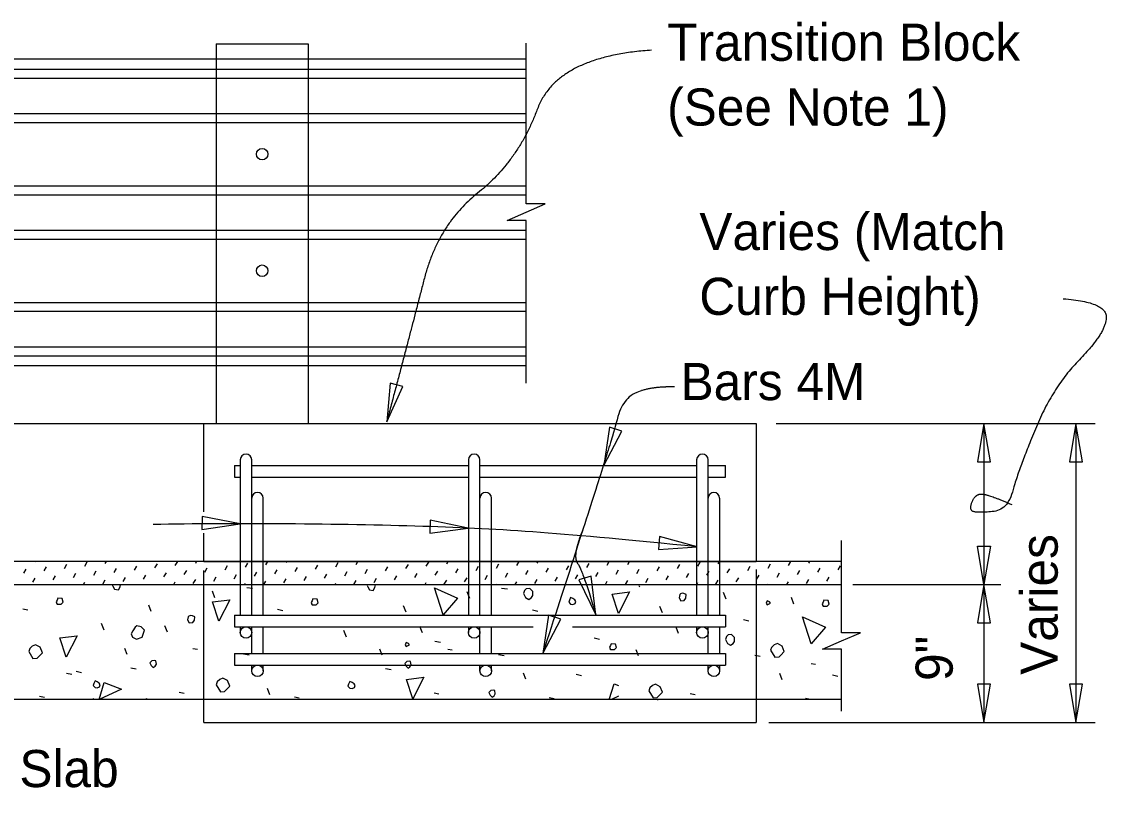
# Model space of a CAD drawing. Extents: x 21526.6 to 21595.9, y 56117 to 56157.3.
# Drawn here: x 21561.42 to 21567.31, y 56133.17 to 56137.39 of the extents above; entities that cross this region are included whole.
import ezdxf

# ---------------------------------------------------------------- set-up
doc = ezdxf.new("R2010")
doc.units = 0
for name, color, linetype in [('AdhocPoint_dp', 7, 'Continuous'), ('Border', 7, 'Continuous'), ('Patterning', 7, 'Continuous'), ('PlotBorder_dp', 7, 'Continuous'), ('SheetBorder_dp', 7, 'Continuous'), ('SheetLines_dp', 7, 'Continuous'), ('SubStrConc', 7, 'Continuous'), ('SubStrConc_h', 7, 'Continuous')]:
    doc.layers.add(name, color=color, linetype=linetype)

msp = doc.modelspace()

# ---------------------------------------------------------------- linework, layer by layer
at = {"layer": 'AdhocPoint_dp'}
for p, q in [((21554.3018, 56135.21), (21562.4118, 56135.21)), ((21565.8764, 56134.4601), (21554.3018, 56134.4601)), ((21554.3018, 56134.3351), (21565.8764, 56134.3351)), ((21565.8764, 56133.71), (21559.5217, 56133.71))]:
    msp.add_line(p, q, dxfattribs=at)
at = {"layer": 'Patterning'}
for p, q in [((21562.4788, 56137.2725), (21562.4788, 56135.21)), ((21562.4788, 56137.2725), (21562.9788, 56137.2725)), ((21562.9788, 56137.2725), (21562.9788, 56135.21)), ((21552.8484, 56137.1336), (21564.1633, 56137.1336)), ((21552.8484, 56137.0853), (21564.1633, 56137.0853)), ((21552.8484, 56136.8925), (21564.1633, 56136.8925)), ((21552.8484, 56136.8443), (21564.1633, 56136.8443)), ((21552.8484, 56136.5003), (21564.1633, 56136.5003)), ((21552.8484, 56136.4521), (21564.1633, 56136.4521)), ((21552.8484, 56136.2593), (21564.1633, 56136.2593)), ((21552.8484, 56136.2112), (21564.1633, 56136.2112)), ((21552.8484, 56135.8672), (21564.1633, 56135.8672)), ((21552.8484, 56135.819), (21564.1633, 56135.819)), ((21552.8484, 56135.6262), (21564.1633, 56135.6262)), ((21552.8484, 56135.5779), (21564.1633, 56135.5779)), ((21561.4336, 56134.3964), (21561.4465, 56134.4187)), ((21561.4954, 56134.4582), (21561.4965, 56134.4601)), ((21561.5442, 56134.4093), (21561.5572, 56134.4317)), ((21561.6548, 56134.4223), (21561.6678, 56134.4447)), ((21561.7655, 56134.4352), (21561.7784, 56134.4576)), ((21561.8761, 56134.4482), (21561.883, 56134.4601)), ((21561.9249, 56134.3994), (21561.9379, 56134.4218)), ((21562.0356, 56134.4123), (21562.0485, 56134.4347)), ((21562.1462, 56134.4253), (21562.1592, 56134.4477)), ((21562.2568, 56134.4383), (21562.2695, 56134.4601)), ((21562.3675, 56134.4512), (21562.3726, 56134.4601)), ((21562.4163, 56134.4024), (21562.4293, 56134.4248)), ((21562.5269, 56134.4154), (21562.5399, 56134.4377)), ((21562.6376, 56134.4283), (21562.6505, 56134.4507)), ((21562.7482, 56134.4413), (21562.7591, 56134.4601)), ((21562.8588, 56134.4542), (21562.8622, 56134.4601)), ((21562.9077, 56134.4054), (21562.9206, 56134.4278)), ((21563.0183, 56134.4184), (21563.0312, 56134.4408)), ((21563.1289, 56134.4313), (21563.1419, 56134.4537)), ((21563.2396, 56134.4443), (21563.2487, 56134.4601)), ((21563.2884, 56134.3955), (21563.3013, 56134.4179)), ((21563.3502, 56134.4573), (21563.3518, 56134.4601)), ((21563.399, 56134.4084), (21563.412, 56134.4308)), ((21563.5097, 56134.4214), (21563.5226, 56134.4438)), ((21563.6203, 56134.4344), (21563.6332, 56134.4568)), ((21563.7309, 56134.4473), (21563.7383, 56134.4601)), ((21563.7798, 56134.3985), (21563.7927, 56134.4209)), ((21563.8904, 56134.4115), (21563.9033, 56134.4338)), ((21564.001, 56134.4244), (21564.014, 56134.4468)), ((21564.1116, 56134.4374), (21564.1246, 56134.4598)), ((21564.2223, 56134.4503), (21564.2279, 56134.4601)), ((21564.2711, 56134.4015), (21564.2841, 56134.4239)), ((21564.3817, 56134.4145), (21564.3947, 56134.4369)), ((21564.4924, 56134.4274), (21564.5053, 56134.4498)), ((21564.603, 56134.4404), (21564.6144, 56134.4601)), ((21564.7151, 56134.4443), (21564.7243, 56134.4601)), ((21564.764, 56134.3955), (21564.7769, 56134.4179)), ((21564.8258, 56134.4573), (21564.8274, 56134.4601)), ((21564.8746, 56134.4084), (21564.8876, 56134.4308)), ((21564.9852, 56134.4214), (21564.9982, 56134.4438)), ((21565.0959, 56134.4344), (21565.1088, 56134.4568)), ((21565.2065, 56134.4473), (21565.2139, 56134.4601)), ((21565.2553, 56134.3985), (21565.2683, 56134.4209)), ((21565.366, 56134.4115), (21565.3789, 56134.4338)), ((21565.4766, 56134.4244), (21565.4896, 56134.4468)), ((21565.5872, 56134.4374), (21565.6002, 56134.4598)), ((21565.6979, 56134.4503), (21565.7035, 56134.4601)), ((21565.7467, 56134.4015), (21565.7597, 56134.4239)), ((21565.8573, 56134.4145), (21565.8703, 56134.4369)), ((21561.4824, 56134.3475), (21561.4954, 56134.3699)), ((21561.593, 56134.3605), (21561.606, 56134.3829)), ((21561.7037, 56134.3734), (21561.7166, 56134.3958)), ((21561.8143, 56134.3864), (21561.8273, 56134.4088)), ((21561.8631, 56134.3376), (21561.8761, 56134.36)), ((21561.9738, 56134.3505), (21561.9867, 56134.3729)), ((21562.0844, 56134.3635), (21562.0974, 56134.3859)), ((21562.195, 56134.3765), (21562.208, 56134.3989)), ((21562.3057, 56134.3894), (21562.3186, 56134.4118)), ((21562.3545, 56134.3406), (21562.3675, 56134.363)), ((21562.4651, 56134.3536), (21562.4781, 56134.376)), ((21562.5758, 56134.3665), (21562.5887, 56134.3889)), ((21562.6864, 56134.3795), (21562.6994, 56134.4019)), ((21562.797, 56134.3925), (21562.81, 56134.4148)), ((21562.8459, 56134.3436), (21562.8588, 56134.366)), ((21562.9565, 56134.3566), (21562.9695, 56134.379)), ((21563.0671, 56134.3695), (21563.0801, 56134.3919)), ((21563.1778, 56134.3825), (21563.1907, 56134.4049)), ((21563.3372, 56134.3466), (21563.3502, 56134.369)), ((21563.4479, 56134.3596), (21563.4608, 56134.382)), ((21563.5585, 56134.3726), (21563.5714, 56134.395)), ((21563.6691, 56134.3855), (21563.6821, 56134.4079)), ((21563.718, 56134.3367), (21563.7309, 56134.3591)), ((21563.8286, 56134.3497), (21563.8415, 56134.372)), ((21563.9392, 56134.3626), (21563.9522, 56134.385)), ((21564.0499, 56134.3756), (21564.0628, 56134.398)), ((21564.1605, 56134.3885), (21564.1734, 56134.4109)), ((21564.2093, 56134.3397), (21564.2223, 56134.3621)), ((21564.32, 56134.3527), (21564.3329, 56134.3751)), ((21564.4306, 56134.3656), (21564.4435, 56134.388)), ((21564.5412, 56134.3786), (21564.5542, 56134.401)), ((21564.6518, 56134.3916), (21564.6648, 56134.414)), ((21564.8128, 56134.3466), (21564.8258, 56134.369)), ((21564.9234, 56134.3596), (21564.9364, 56134.382)), ((21565.0341, 56134.3726), (21565.047, 56134.395)), ((21565.1447, 56134.3855), (21565.1577, 56134.4079)), ((21565.1935, 56134.3367), (21565.2065, 56134.3591)), ((21565.3042, 56134.3497), (21565.3171, 56134.372)), ((21565.4148, 56134.3626), (21565.4278, 56134.385)), ((21565.5254, 56134.3756), (21565.5384, 56134.398)), ((21565.6361, 56134.3885), (21565.649, 56134.4109)), ((21565.6849, 56134.3397), (21565.6979, 56134.3621)), ((21565.7955, 56134.3527), (21565.8085, 56134.3751)), ((21561.7585, 56134.3351), (21561.7655, 56134.347)), ((21562.145, 56134.3351), (21562.1462, 56134.3371)), ((21562.2482, 56134.3351), (21562.2568, 56134.35)), ((21562.6346, 56134.3351), (21562.6376, 56134.3401)), ((21562.6448, 56134.3185), (21562.6766, 56134.315)), ((21562.7378, 56134.3351), (21562.7482, 56134.353)), ((21563.1243, 56134.3351), (21563.1289, 56134.3431)), ((21563.2274, 56134.3351), (21563.2396, 56134.3561)), ((21563.6139, 56134.3351), (21563.6203, 56134.3461)), ((21564.0004, 56134.3351), (21564.001, 56134.3362)), ((21564.0294, 56134.315), (21564.0613, 56134.3114)), ((21564.1035, 56134.3351), (21564.1116, 56134.3491)), ((21564.49, 56134.3351), (21564.4924, 56134.3392)), ((21564.5931, 56134.3351), (21564.603, 56134.3522)), ((21564.703, 56134.3351), (21564.7151, 56134.3561)), ((21565.0895, 56134.3351), (21565.0959, 56134.3461)), ((21565.476, 56134.3351), (21565.4766, 56134.3362)), ((21565.5791, 56134.3351), (21565.5872, 56134.3491)), ((21562.4721, 56134.2625), (21562.458, 56134.2979)), ((21563.8568, 56134.259), (21563.8427, 56134.2944)), ((21565.2489, 56134.2557), (21565.2347, 56134.291)), ((21565.6176, 56134.2282), (21565.6035, 56134.2636)), ((21561.428, 56134.2036), (21561.4563, 56134.1965)), ((21562.1263, 56134.1877), (21562.1121, 56134.223)), ((21562.8127, 56134.2001), (21562.841, 56134.193)), ((21563.511, 56134.1841), (21563.4968, 56134.2195)), ((21564.1974, 56134.1965), (21564.2257, 56134.1894)), ((21564.903, 56134.1808), (21564.8889, 56134.2161)), ((21561.87, 56134.0869), (21561.8558, 56134.1223)), ((21565.3441, 56134.1447), (21565.3724, 56134.1376)), ((21562.214, 56134.0752), (21562.1999, 56134.1105)), ((21563.1862, 56134.0491), (21563.172, 56134.0845)), ((21563.5987, 56134.0716), (21563.5846, 56134.107)), ((21564.9908, 56134.0683), (21564.9767, 56134.1036)), ((21563.6672, 56134.0268), (21563.6973, 56134.0215)), ((21564.5329, 56134.0454), (21564.5612, 56134.0384)), ((21561.9955, 56133.9543), (21561.9831, 56133.9879)), ((21562.3519, 56133.9868), (21562.3767, 56133.9832)), ((21562.6277, 56133.9585), (21562.6578, 56133.9532)), ((21563.3802, 56133.9508), (21563.3678, 56133.9844)), ((21563.7366, 56133.9832), (21563.7614, 56133.9797)), ((21564.0124, 56133.955), (21564.0424, 56133.9497)), ((21564.7722, 56133.9474), (21564.7598, 56133.981)), ((21565.4045, 56133.9516), (21565.4345, 56133.9463)), ((21565.7105, 56133.9057), (21565.7353, 56133.9022)), ((21561.6655, 56133.8542), (21561.6938, 56133.8471)), ((21561.7179, 56133.8642), (21561.7462, 56133.8571)), ((21562.0143, 56133.8825), (21562.0443, 56133.8772)), ((21563.399, 56133.8789), (21563.429, 56133.8736)), ((21564.1609, 56133.8206), (21564.1485, 56133.8542)), ((21564.4349, 56133.8471), (21564.4632, 56133.8401)), ((21565.5529, 56133.8173), (21565.5406, 56133.8508)), ((21565.8269, 56133.8438), (21565.8552, 56133.8367)), ((21562.7705, 56133.7357), (21562.7581, 56133.7693)), ((21561.5188, 56133.7287), (21561.5453, 56133.7234)), ((21561.8135, 56133.71), (21561.8116, 56133.7152)), ((21562.2777, 56133.7499), (21562.3042, 56133.7446)), ((21562.9035, 56133.7251), (21562.93, 56133.7198)), ((21563.1969, 56133.71), (21563.1963, 56133.7116)), ((21563.6624, 56133.7464), (21563.6889, 56133.7411)), ((21564.2882, 56133.7216), (21564.3147, 56133.7163)), ((21565.0544, 56133.743), (21565.0809, 56133.7377)), ((21565.6802, 56133.7183), (21565.7067, 56133.713))]:
    msp.add_line(p, q, dxfattribs=at)
for points in [[(21561.915, 56134.3351), (21561.9142, 56134.3326), (21561.9177, 56134.3256)], [(21561.9177, 56134.3256), (21561.9265, 56134.3097), (21561.9477, 56134.3061), (21561.9566, 56134.322), (21561.9598, 56134.3351)], [(21563.3008, 56134.3351), (21563.2988, 56134.3291), (21563.3024, 56134.322)], [(21563.3024, 56134.322), (21563.3112, 56134.3061), (21563.3324, 56134.3026), (21563.3413, 56134.3185), (21563.3448, 56134.3326), (21563.3424, 56134.3351)], [(21563.7121, 56134.1696), (21563.6644, 56134.3163), (21563.7899, 56134.2615), (21563.7121, 56134.1696)], [(21564.1486, 56134.2859), (21564.1592, 56134.2647), (21564.1769, 56134.2541), (21564.191, 56134.2647), (21564.1981, 56134.2753), (21564.1981, 56134.2965), (21564.1822, 56134.3124), (21564.1627, 56134.3106), (21564.1539, 56134.3018), (21564.1486, 56134.2859)], [(21564.7764, 56134.3351), (21564.7744, 56134.3291), (21564.7779, 56134.322)], [(21561.6154, 56134.2283), (21561.6366, 56134.2283), (21561.6472, 56134.2389), (21561.6419, 56134.2584), (21561.6189, 56134.2602), (21561.6154, 56134.2495), (21561.6101, 56134.2407), (21561.6154, 56134.2283), (21561.6119, 56134.2319)], [(21562.4929, 56134.1357), (21562.4593, 56134.24), (21562.553, 56134.2524), (21562.4929, 56134.1357)], [(21563.0001, 56134.2248), (21563.0213, 56134.2248), (21563.0319, 56134.2354), (21563.0266, 56134.2549), (21563.0036, 56134.2566), (21563.0001, 56134.246), (21562.9948, 56134.2372), (21563.0001, 56134.2248), (21562.9965, 56134.2283)], [(21564.4044, 56134.2281), (21564.4168, 56134.2263), (21564.4292, 56134.2316), (21564.4327, 56134.2423), (21564.4274, 56134.2511), (21564.4168, 56134.2582), (21564.4044, 56134.2635), (21564.3973, 56134.2493), (21564.3938, 56134.2387), (21564.4044, 56134.2281)], [(21564.6643, 56134.1779), (21564.6307, 56134.2822), (21564.7244, 56134.2945), (21564.6643, 56134.1779)], [(21564.9933, 56134.2627), (21565.0022, 56134.2468), (21565.0216, 56134.2485), (21565.0304, 56134.2609), (21565.0322, 56134.2803), (21565.0198, 56134.2856), (21565.011, 56134.2874), (21565.0004, 56134.2839), (21564.9968, 56134.2803), (21564.9933, 56134.2627)], [(21565.4713, 56134.2251), (21565.4908, 56134.2339), (21565.4837, 56134.241), (21565.4713, 56134.2463), (21565.466, 56134.2339), (21565.4713, 56134.2251)], [(21565.7768, 56134.2179), (21565.798, 56134.2179), (21565.8086, 56134.2285), (21565.8033, 56134.248), (21565.7804, 56134.2497), (21565.7768, 56134.2391), (21565.7715, 56134.2303), (21565.7768, 56134.2179), (21565.7733, 56134.2215)], [(21562.3237, 56134.1423), (21562.3325, 56134.1264), (21562.3519, 56134.1282), (21562.3608, 56134.1406), (21562.3625, 56134.16), (21562.3502, 56134.1653), (21562.3413, 56134.1671), (21562.3307, 56134.1636), (21562.3272, 56134.16), (21562.3237, 56134.1423)], [(21565.7117, 56134.0122), (21565.664, 56134.1589), (21565.7895, 56134.1041), (21565.7117, 56134.0122)], [(21562.0238, 56134.0498), (21562.0467, 56134.0374), (21562.0768, 56134.0498), (21562.0892, 56134.0869), (21562.0715, 56134.1046), (21562.0485, 56134.1099), (21562.0379, 56134.1028), (21562.0255, 56134.0834), (21562.0167, 56134.0675), (21562.0238, 56134.0498)], [(21561.4605, 56133.9709), (21561.4834, 56133.9337), (21561.5064, 56133.9355), (21561.5153, 56133.9444), (21561.5347, 56133.9638), (21561.5223, 56133.9938), (21561.4976, 56134.008), (21561.4799, 56134.0009), (21561.4658, 56133.9868), (21561.4605, 56133.9709)], [(21561.6631, 56133.9402), (21561.6295, 56134.0445), (21561.7232, 56134.0569), (21561.6631, 56133.9402)], [(21563.5103, 56133.998), (21563.5298, 56134.0068), (21563.5227, 56134.0139), (21563.5103, 56134.0192), (21563.505, 56134.0068), (21563.5103, 56133.998)], [(21564.6215, 56133.9816), (21564.6427, 56133.9816), (21564.6533, 56133.9922), (21564.648, 56134.0116), (21564.625, 56134.0134), (21564.6215, 56134.0028), (21564.6162, 56133.994), (21564.6215, 56133.9816), (21564.618, 56133.9851)], [(21565.2454, 56134.0365), (21565.256, 56134.0152), (21565.2736, 56134.0046), (21565.2878, 56134.0152), (21565.2948, 56134.0259), (21565.2948, 56134.0471), (21565.2789, 56134.063), (21565.2595, 56134.0612), (21565.2507, 56134.0524), (21565.2454, 56134.0365)], [(21565.4907, 56133.9776), (21565.5137, 56133.9404), (21565.5366, 56133.9422), (21565.5455, 56133.9511), (21565.5649, 56133.9705), (21565.5526, 56134.0005), (21565.5278, 56134.0147), (21565.5101, 56134.0076), (21565.496, 56133.9935), (21565.4907, 56133.9776)], [(21562.1257, 56133.8949), (21562.1363, 56133.8842), (21562.1469, 56133.8913), (21562.1539, 56133.9019), (21562.1504, 56133.9196), (21562.1416, 56133.9214), (21562.1292, 56133.9196), (21562.1186, 56133.909), (21562.1257, 56133.8949)], [(21563.5103, 56133.8913), (21563.5209, 56133.8807), (21563.5316, 56133.8878), (21563.5386, 56133.8984), (21563.5351, 56133.9161), (21563.5262, 56133.9178), (21563.5139, 56133.9161), (21563.5033, 56133.9055), (21563.5103, 56133.8913)], [(21563.547, 56133.7141), (21563.5134, 56133.8184), (21563.6071, 56133.8308), (21563.547, 56133.7141)], [(21561.8205, 56133.7758), (21561.8328, 56133.774), (21561.8452, 56133.7793), (21561.8487, 56133.7899), (21561.8434, 56133.7988), (21561.8328, 56133.8058), (21561.8205, 56133.8111), (21561.8134, 56133.797), (21561.8099, 56133.7864), (21561.8205, 56133.7758)], [(21561.8428, 56133.711), (21561.8711, 56133.8029), (21561.9648, 56133.7658), (21561.8428, 56133.711)], [(21562.4785, 56133.7897), (21562.5015, 56133.7526), (21562.5245, 56133.7544), (21562.5333, 56133.7632), (21562.5528, 56133.7827), (21562.5404, 56133.8127), (21562.5156, 56133.8269), (21562.498, 56133.8198), (21562.4838, 56133.8056), (21562.4785, 56133.7897)], [(21563.2051, 56133.7723), (21563.2175, 56133.7705), (21563.2299, 56133.7758), (21563.2334, 56133.7864), (21563.2281, 56133.7952), (21563.2175, 56133.8023), (21563.2051, 56133.8076), (21563.1981, 56133.7935), (21563.1945, 56133.7829), (21563.2051, 56133.7723)], [(21564.6141, 56133.71), (21564.6405, 56133.7959), (21564.6652, 56133.7861)], [(21564.8288, 56133.7569), (21564.8518, 56133.7198), (21564.8748, 56133.7216), (21564.8836, 56133.7304), (21564.9031, 56133.7499), (21564.8907, 56133.7799), (21564.8659, 56133.794), (21564.8483, 56133.787), (21564.8341, 56133.7728), (21564.8288, 56133.7569)], [(21562.1099, 56133.71), (21562.1009, 56133.7145), (21562.0934, 56133.71)], [(21563.4875, 56133.71), (21563.4856, 56133.711), (21563.484, 56133.71)], [(21563.9669, 56133.7339), (21563.9775, 56133.7233), (21563.9881, 56133.7304), (21563.9951, 56133.741), (21563.9916, 56133.7586), (21563.9828, 56133.7604), (21563.9704, 56133.7586), (21563.9598, 56133.748), (21563.9669, 56133.7339)], [(21564.6652, 56133.7277), (21564.6258, 56133.71)], [(21564.8796, 56133.7067), (21564.8777, 56133.7077), (21564.876, 56133.7067)]]:
    msp.add_lwpolyline(points, dxfattribs=at)
at = {"layer": 'PlotBorder_dp'}
for p, q in [((21565.5209, 56135.21), (21567.2532, 56135.21)), ((21566.6495, 56135.21), (21566.6495, 56133.585)), ((21567.1495, 56135.21), (21567.1495, 56133.585)), ((21565.9364, 56134.335), (21566.742, 56134.335)), ((21565.4809, 56133.585), (21567.2532, 56133.585))]:
    msp.add_line(p, q, dxfattribs=at)
for points in [[(21564.1633, 56135.429), (21564.1633, 56136.3122), (21564.0599, 56136.3122), (21564.1633, 56136.3572), (21564.2666, 56136.4022), (21564.1633, 56136.4022), (21564.1633, 56137.2752)], [(21565.8764, 56133.6472), (21565.8764, 56133.9832), (21565.7731, 56133.9832), (21565.8764, 56134.0282), (21565.9797, 56134.0732), (21565.8764, 56134.0732), (21565.8764, 56134.5731)]]:
    msp.add_lwpolyline(points, dxfattribs=at)
for points in [[(21563.4053, 56135.2188), (21563.4928, 56135.4111), (21563.4245, 56135.4291)], [(21564.5839, 56134.9808), (21564.6819, 56135.1679), (21564.6148, 56135.1898)], [(21566.6495, 56135.21), (21566.6142, 56135.0017), (21566.6848, 56135.0017)], [(21567.1495, 56135.21), (21567.1142, 56135.0017), (21567.1848, 56135.0017)], [(21562.6093, 56134.6644), (21562.4019, 56134.7045), (21562.4003, 56134.634)], [(21563.8483, 56134.6403), (21563.6418, 56134.6846), (21563.6388, 56134.6141)], [(21565.0916, 56134.5393), (21564.8879, 56134.5955), (21564.8808, 56134.5253)], [(21566.6495, 56134.335), (21566.6142, 56134.5432), (21566.6848, 56134.5432)], [(21564.5411, 56134.1696), (21564.5162, 56134.3794), (21564.4485, 56134.3595)], [(21566.6495, 56134.335), (21566.6142, 56134.1267), (21566.6848, 56134.1267)], [(21564.2526, 56133.9599), (21564.3506, 56134.147), (21564.2835, 56134.1689)], [(21566.6495, 56133.585), (21566.6848, 56133.7933), (21566.6142, 56133.7933)], [(21567.1495, 56133.585), (21567.1848, 56133.7933), (21567.1142, 56133.7933)]]:
    msp.add_lwpolyline(points, close=True, dxfattribs=at)
for points, degree in [([(21564.8436, 56137.2374), (21564.3295, 56137.2022), (21564.1187, 56136.6348), (21563.685, 56136.2922), (21563.5309, 56135.6927), (21563.4053, 56135.2188)], 2), ([(21567.0807, 56135.8873), (21567.3138, 56135.8697), (21567.3147, 56135.7056), (21567.0236, 56135.4087), (21566.8353, 56134.952), (21566.7782, 56134.7407), (21566.6298, 56134.7236), (21566.5671, 56134.735), (21566.6013, 56134.8264), (21566.6698, 56134.8264), (21566.8011, 56134.7693)], 2), ([(21564.9691, 56135.4078), (21564.8456, 56135.4112), (21564.6854, 56135.3477), (21564.6319, 56135.124), (21564.2525, 56133.9599)], 2), ([(21565.0915, 56134.5393), (21564.3611, 56134.6135), (21563.7373, 56134.6604), (21562.5671, 56134.6688), (21562.1373, 56134.6608)], 3), ([(21564.4705, 56134.6317), (21564.412, 56134.4912), (21564.4698, 56134.4123), (21564.5411, 56134.1696)], 2)]:
    msp.add_open_spline(points, degree=degree, dxfattribs=at)
at = {"layer": 'SheetBorder_dp'}
for p, q in [((21564.1633, 56137.1891), (21552.8484, 56137.1891)), ((21564.1633, 56135.5224), (21552.8484, 56135.5224))]:
    msp.add_line(p, q, dxfattribs=at)
for centre in [(21562.7288, 56136.6724), (21562.7288, 56136.0393)]:
    msp.add_circle(centre, 0.0312, dxfattribs=at)
at = {"layer": 'SheetLines_dp'}
for p, q in [((21562.6097, 56135.0121), (21562.6097, 56134.1683)), ((21562.6722, 56134.1683), (21562.6722, 56135.0121)), ((21563.8493, 56135.0121), (21563.8493, 56134.1683)), ((21563.9118, 56134.1683), (21563.9118, 56135.0121)), ((21565.0889, 56135.0121), (21565.0889, 56134.1683)), ((21565.1514, 56134.1683), (21565.1514, 56135.0121)), ((21562.5785, 56134.9808), (21562.6097, 56134.9808)), ((21562.5785, 56134.9808), (21562.5785, 56134.9183)), ((21562.6722, 56134.9808), (21563.8493, 56134.9808)), ((21563.9118, 56134.9808), (21565.0889, 56134.9808)), ((21565.1514, 56134.9808), (21565.2451, 56134.9808)), ((21565.2451, 56134.9183), (21565.2451, 56134.9808)), ((21562.5785, 56134.9183), (21562.6097, 56134.9183)), ((21562.6722, 56134.9183), (21563.8493, 56134.9183)), ((21563.9118, 56134.9183), (21565.0889, 56134.9183)), ((21565.1514, 56134.9183), (21565.2451, 56134.9183)), ((21562.7347, 56134.1683), (21562.7347, 56134.8038)), ((21563.9743, 56134.1683), (21563.9743, 56134.8038)), ((21565.2139, 56134.1683), (21565.2139, 56134.8038)), ((21562.5785, 56134.1683), (21562.5785, 56134.1058)), ((21562.5785, 56134.1683), (21565.2451, 56134.1683)), ((21565.2451, 56134.1683), (21565.2451, 56134.1058)), ((21562.5785, 56134.1058), (21564.1999, 56134.1058)), ((21562.6097, 56134.1058), (21562.6097, 56134.0745)), ((21562.6722, 56133.9599), (21562.6722, 56134.1058)), ((21562.7347, 56133.9599), (21562.7347, 56134.1058)), ((21563.8493, 56134.1058), (21563.8493, 56134.0745)), ((21563.9118, 56133.9599), (21563.9118, 56134.1058)), ((21563.9743, 56133.9599), (21563.9743, 56134.1058)), ((21564.4139, 56134.1058), (21565.2451, 56134.1058)), ((21565.0889, 56134.1058), (21565.0889, 56134.0745)), ((21565.1514, 56133.9599), (21565.1514, 56134.1058)), ((21565.2139, 56133.9599), (21565.2139, 56134.1058)), ((21562.5785, 56133.9599), (21562.5785, 56133.8975)), ((21562.5785, 56133.9599), (21565.2451, 56133.9599)), ((21565.2451, 56133.9599), (21565.2451, 56133.8975)), ((21562.5785, 56133.8975), (21565.2451, 56133.8975)), ((21562.6722, 56133.8662), (21562.6722, 56133.8975)), ((21562.7347, 56133.8662), (21562.7347, 56133.8975)), ((21563.9118, 56133.8662), (21563.9118, 56133.8975)), ((21563.9743, 56133.8662), (21563.9743, 56133.8975)), ((21565.1514, 56133.8662), (21565.1514, 56133.8975)), ((21565.2139, 56133.8662), (21565.2139, 56133.8975))]:
    msp.add_line(p, q, dxfattribs=at)
for centre in [(21562.6409, 56134.0745), (21563.8805, 56134.0745), (21565.1201, 56134.0745), (21562.7034, 56133.8662), (21563.943, 56133.8662), (21565.1826, 56133.8662)]:
    msp.add_circle(centre, 0.0312, dxfattribs=at)
for centre, radius, start, end in [((21562.6409, 56135.0121), 0.0312, 0, 180), ((21563.8805, 56135.0121), 0.0312, 0, 180), ((21565.1201, 56135.0121), 0.0312, 0, 180), ((21562.7034, 56134.8038), 0.0312, 0, 180), ((21563.943, 56134.8038), 0.0312, 0, 180), ((21565.1826, 56134.8038), 0.0312, 0, 180), ((21562.8709, 56133.1683), 1, 90, 90.00000277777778)]:
    msp.add_arc(centre, radius, start, end, dxfattribs=at)
at = {"layer": 'SubStrConc'}
for p, q in [((21562.4118, 56135.21), (21565.4118, 56135.21)), ((21562.4118, 56134.7288), (21562.4118, 56135.21)), ((21565.4118, 56135.21), (21565.4118, 56134.46)), ((21562.4118, 56134.46), (21562.4118, 56134.6132))]:
    msp.add_line(p, q, dxfattribs=at)
at = {"layer": 'SubStrConc_h'}
for p, q in [((21562.4118, 56134.46), (21565.4118, 56134.46)), ((21565.4118, 56134.417), (21565.4118, 56133.585)), ((21562.4118, 56133.585), (21562.4118, 56134.4115)), ((21562.4118, 56133.585), (21565.4118, 56133.585))]:
    msp.add_line(p, q, dxfattribs=at)

# ---------------------------------------------------------------- texts
at = {"layer": 'Border'}
for s, p in [('Bars 4M', (21565.0015, 56135.3365)), ('Existing Approach Slab', (21559.1619, 56133.2344))]:
    msp.add_text(s, height=0.2016, dxfattribs=at).set_placement(p)
for s, p in [('Varies', (21567.0502, 56133.8443)), ('9"', (21566.4798, 56133.8109))]:
    msp.add_text(s, height=0.2016, rotation=90, dxfattribs=at).set_placement(p)
at = {"layer": 'PlotBorder_dp'}
for s, p in [('Transition Block', (21564.9286, 56137.1797)), ('(See Note 1)', (21564.9286, 56136.8277)), ('Varies (Match', (21565.1035, 56136.1516)), ('Curb Height)', (21565.1035, 56135.7996))]:
    msp.add_text(s, height=0.2016, dxfattribs=at).set_placement(p)

doc.saveas('drawing.dxf')
